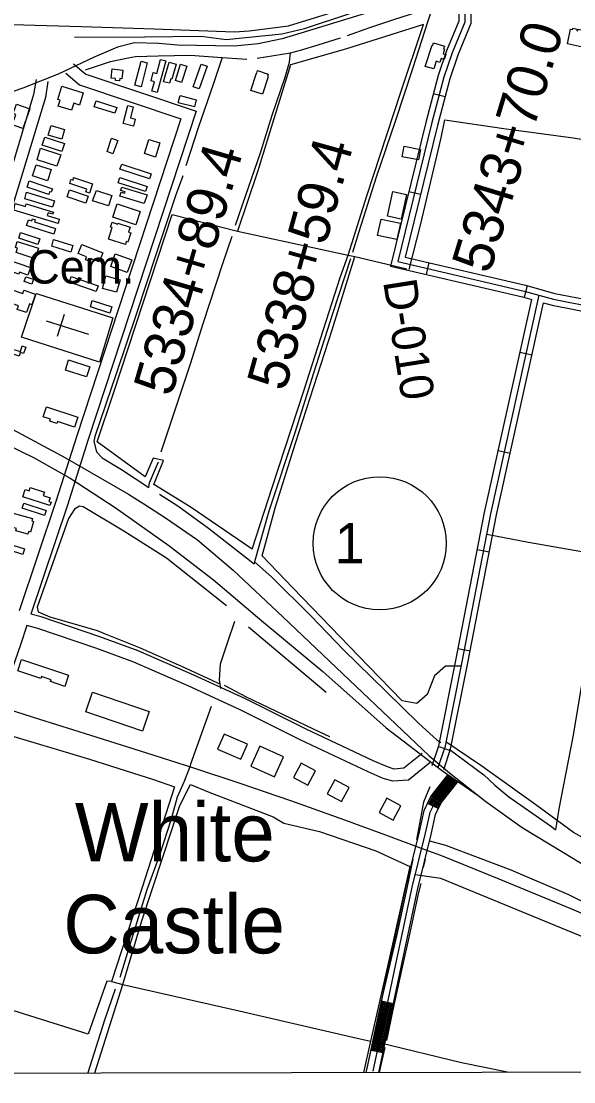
# Model space of a CAD drawing. Extents: x 3324125 to 3362000, y 600753 to 626151.
# Drawn here: x 3340770 to 3342140, y 606134 to 608764 of the extents above; entities that cross this region are included whole.
import ezdxf

# ---------------------------------------------------------------- set-up
doc = ezdxf.new("R2010")
doc.units = 0
for name, color, linetype in [('V-BLDG-OTLN', 7, 'Continuous'), ('V-DTCH-CNTR', 7, 'Continuous'), ('V-GRID-FRAM', 7, 'Continuous'), ('V-LEVE-TOET', 7, 'Continuous'), ('V-RAIL-TRAK', 7, 'Continuous'), ('V-RIVR-RANG-IDEN', 7, 'Continuous'), ('V-ROAD-CNTR', 7, 'Continuous'), ('V-ROAD-IDEN', 7, 'Continuous'), ('V-SITE-OTLN', 7, 'Continuous'), ('V-SITE-OTLN-IDEN', 7, 'Continuous'), ('V-SURV-IDEN', 7, 'Continuous'), ('V-TOPO-GNAM-IDEN', 7, 'Continuous'), ('V-TOPO-SHOR', 7, 'Continuous')]:
    doc.layers.add(name, color=color, linetype=linetype)

msp = doc.modelspace()

# ---------------------------------------------------------------- linework, layer by layer
at = {"layer": 'V-BLDG-OTLN'}
for points in [[(3342124.1, 608707.7), (3342131.5, 608744.4), (3342136.6, 608743.3), (3342137.4, 608746.9), (3342148.2, 608744.5), (3342147.4, 608740.8), (3342149.2, 608740.4), (3342150.1, 608744.6), (3342168.6, 608740.6), (3342163.5, 608717.5), (3342172.5, 608715.6), (3342168.6, 608697.9)], [(3341771.6, 608652.1), (3341788.3, 608705), (3341790.3, 608704.3), (3341792.2, 608710.4), (3341819.1, 608701.8), (3341817, 608695.2), (3341819.5, 608694.4), (3341816, 608683.4), (3341822.3, 608681.4), (3341818.5, 608669.5), (3341810.8, 608672), (3341807.6, 608661.7), (3341798.5, 608664.6), (3341792.7, 608645.6)], [(3341052.2, 608605.6), (3341067.4, 608664.7), (3341082.6, 608660.8), (3341067.4, 608601.5)], [(3341107.5, 608587.1), (3341094.3, 608590.7), (3341100.5, 608614.1), (3341091.9, 608616.3), (3341097.3, 608636.7), (3341106.3, 608634.3), (3341115.6, 608669.5), (3341128.3, 608666.1)], [(3340992.9, 608622.7), (3340995.6, 608645.9), (3341022.2, 608642.8), (3341019.7, 608621.2), (3341014.6, 608621.8), (3341013.9, 608615.9), (3341003.8, 608617.1), (3341004.3, 608621.7)], [(3341122.5, 608613.5), (3341137.1, 608662.5), (3341154.5, 608657.3), (3341143.6, 608620.7), (3341141.2, 608621.4), (3341137.9, 608610.3)], [(3341152.2, 608617.2), (3341165, 608657.2), (3341180.5, 608652.2), (3341167.7, 608612.3)], [(3341231.4, 608652.2), (3341211.3, 608596.3), (3341196.2, 608601.7), (3341216.4, 608657.6)], [(3341338.9, 608592.6), (3341353, 608635.6), (3341354.1, 608635.2), (3341356.1, 608641.5), (3341382.5, 608632.9), (3341380.4, 608626.6), (3341382.3, 608626), (3341368.3, 608583)], [(3340870.9, 608603), (3340923.8, 608586.8), (3340914.4, 608556.2), (3340900.4, 608560.5), (3340895.2, 608543.7), (3340862.1, 608553.8), (3340866.6, 608568.6), (3340860.9, 608570.3)], [(3340743.5, 608508.8), (3340747, 608522.4), (3340752.8, 608520.4), (3340757.1, 608532.8), (3340750.2, 608535.2), (3340758.4, 608558.6), (3340791.3, 608547.1), (3340774.1, 608498.1)], [(3340951.3, 608552.1), (3340955.6, 608566.5), (3341006.9, 608550.3), (3341002.4, 608536)], [(3341159.2, 608561.6), (3341164.3, 608580.2), (3341204.2, 608569.3), (3341199.8, 608551.5)], [(3341022.9, 608510.5), (3341034.3, 608554.8), (3341047.7, 608551.6), (3341041, 608524.1), (3341052.6, 608521.3), (3341048.4, 608504.2)], [(3340837.1, 608481.6), (3340844.2, 608505.7), (3340877.7, 608495.7), (3340870.5, 608471.6)], [(3340828.7, 608476.3), (3340877.4, 608460.8), (3340871.3, 608441.4), (3340822.1, 608457.1)], [(3340994.3, 608474.3), (3341009.9, 608468.4), (3340997.6, 608435.5), (3340983.5, 608440.8)], [(3341114, 608462.3), (3341102.8, 608427.3), (3341075.7, 608436), (3341086.9, 608471)], [(3341714.1, 608428.2), (3341719.2, 608454.2), (3341759.8, 608446.2), (3341754.7, 608420.2)], [(3340818.3, 608449.2), (3340868.1, 608433), (3340858.8, 608404.5), (3340809.4, 608420.6)], [(3340807.3, 608408.1), (3340844.2, 608396.4), (3340835.4, 608368.7), (3340798.6, 608380.4)], [(3341019.8, 608409.6), (3341092.2, 608385.4), (3341088.1, 608373.1), (3341015, 608397.5)], [(3340900.2, 608376.7), (3340946.9, 608360.8), (3340939.1, 608337.9), (3340930.1, 608341), (3340932.5, 608347.8), (3340890.8, 608361.8), (3340893.6, 608371.4), (3340898.8, 608369.9)], [(3341010.3, 608363.6), (3341014.6, 608376.6), (3341082.7, 608354.5), (3341078.5, 608341.5)], [(3340790, 608368.1), (3340847.4, 608348.4), (3340844.5, 608339.8), (3340840.6, 608341.1), (3340838.4, 608334.7), (3340785.1, 608353)], [(3341014.8, 608330.3), (3341017.7, 608340.3), (3341026.9, 608337.5), (3341027.9, 608340.7), (3341016.6, 608344.2), (3341019.3, 608353), (3341082.1, 608333.6), (3341075.3, 608311.7)], [(3340779.3, 608323.9), (3340783.2, 608340.5), (3340852.9, 608319.1), (3340847.9, 608302.8)], [(3340890.2, 608345.7), (3340936.2, 608330.2), (3340930.3, 608312.9), (3340884, 608328.5)], [(3340956.7, 608344.5), (3340994.9, 608332), (3340986.6, 608306.2), (3340947.2, 608319)], [(3341712, 608273.3), (3341677.7, 608280.8), (3341691.1, 608341.8), (3341725.4, 608334.3)], [(3340751.6, 608295.3), (3340755.6, 608312.5), (3340780.9, 608305), (3340782.8, 608311.1), (3340850.4, 608290.9), (3340848.7, 608285.4), (3340836.8, 608288.9), (3340834.8, 608282.2), (3340864.7, 608273.3), (3340861.5, 608262.5)], [(3341008.2, 608311.2), (3341065.3, 608292.2), (3341054.2, 608258.9), (3340996.9, 608278)], [(3340783.6, 608257.5), (3340788, 608271.7), (3340796.5, 608269), (3340798.2, 608274.3), (3340804.7, 608272.2), (3340803, 608266.9), (3340855.4, 608249.9), (3340850.8, 608235.7)], [(3341653.6, 608232.9), (3341662.5, 608273.5), (3341709.9, 608263), (3341701, 608222.5)], [(3340986.5, 608223.8), (3340995.3, 608252.7), (3340991.6, 608253.8), (3340995.4, 608265.5), (3341008.8, 608261.2), (3341009.4, 608263.1), (3341040.4, 608253.1), (3341036.5, 608241.2), (3341041.9, 608239.5), (3341034.5, 608216.3), (3341030.6, 608217.6), (3341028.3, 608210.4)], [(3340760.4, 608218.1), (3340813.3, 608201.2), (3340805, 608175.1), (3340757.5, 608190.3), (3340761.1, 608201.7), (3340756, 608203.4)], [(3340768.7, 608240.4), (3340816.1, 608224.5), (3340811.4, 608210.5), (3340764.4, 608226.3)], [(3340850.5, 608223.2), (3340898.5, 608208), (3340893.2, 608191.2), (3340846.1, 608206.1)], [(3340920.1, 608210.5), (3340972.7, 608189.7), (3340963.8, 608167.2), (3340943.8, 608175.1), (3340941.1, 608168.2), (3340929.5, 608172.8), (3340932.1, 608179.6), (3340911.2, 608187.8)], [(3340733.1, 608174.2), (3340793.3, 608153.5), (3340786.7, 608134.3), (3340765.6, 608141.5), (3340764, 608136.9), (3340721.7, 608151.4), (3340722.3, 608153.1), (3340719.6, 608154.1), (3340723.5, 608165.4), (3340729.2, 608163.5)], [(3341003.3, 608187), (3341044, 608172.8), (3341033, 608141.4), (3340992, 608155.6)], [(3340781.8, 608130.5), (3340800.6, 608124.7), (3340796.8, 608112.5), (3340777.5, 608118.6)], [(3340889.7, 608116.9), (3340894.1, 608130.9), (3340961, 608108), (3340956.2, 608094.1)], [(3340971.5, 608101.7), (3340980.1, 608132.7), (3341015.3, 608122.9), (3341006.7, 608092.2)], [(3340713, 608109.9), (3340773.9, 608089.1), (3340776.7, 608097.2), (3340805.3, 608087.5), (3340796.4, 608061.2), (3340790.4, 608063.3), (3340783.1, 608041.7), (3340760.2, 608049.5), (3340763.2, 608058.4), (3340701.3, 608079.5)], [(3340946.1, 608071.8), (3340995.2, 608055.5), (3340990, 608039.9), (3340942, 608055.8)], [(3340746.4, 607926.5), (3340719.7, 607932.8), (3340723.1, 607947.1), (3340747.9, 607940), (3340750.9, 607950.3), (3340768.1, 607944.9), (3340772.6, 607959.1), (3340781.5, 607956.3), (3340776.3, 607939.9), (3340767.9, 607942.6), (3340765.1, 607933.7), (3340750.1, 607938.4)], [(3340887.7, 607924.2), (3340939.9, 607906.9), (3340931.7, 607882.1), (3340880, 607899.2)], [(3340833, 607807.9), (3340910.3, 607782), (3340902.2, 607757.8), (3340860.4, 607771.8), (3340858.7, 607766.7), (3340841.4, 607772.5), (3340843, 607777.2), (3340824.9, 607783.3)], [(3340841.2, 607563.5), (3340774.2, 607585.2), (3340779.9, 607602.7), (3340789.8, 607599.5), (3340792.5, 607607.9), (3340827.6, 607596.5), (3340824.8, 607587.8), (3340841.6, 607582.3), (3340838.8, 607573.4), (3340844.3, 607571.7)], [(3340772.8, 607556.7), (3340776.4, 607569.1), (3340832.2, 607550.9), (3340828.2, 607538.7)], [(3340689.9, 607520.5), (3340697.1, 607546.4), (3340716.5, 607541), (3340719.8, 607552.6), (3340798, 607530.7), (3340796.4, 607525.1), (3340801, 607523.8), (3340793.6, 607497.4), (3340788.5, 607498.8), (3340786.7, 607492.4), (3340757.2, 607500.7), (3340758.7, 607506.2), (3340729.8, 607514.3), (3340728.5, 607509.7)], [(3340709.6, 607462.3), (3340714.1, 607475.9), (3340778.4, 607455.7), (3340774.1, 607442)], [(3340887.3, 607142.3), (3340878.3, 607114.6), (3340842.5, 607126.6), (3340844.2, 607131.5), (3340820.8, 607139.3), (3340819.1, 607134.3), (3340761.9, 607153.4), (3340771.2, 607181.1)], [(3340930.2, 607051.6), (3340946.6, 607100.4), (3341087.6, 607052.9), (3341071.1, 607004.1)], [(3341256.8, 606959.4), (3341314.5, 606934), (3341330.9, 606971.4), (3341273.2, 606996.7)], [(3341339.4, 606917), (3341398.1, 606891), (3341419.9, 606940.5), (3341361.2, 606966.4)], [(3341499.4, 606905.1), (3341464.1, 606924.1), (3341445.2, 606888.8), (3341480.4, 606869.9)], [(3341582.7, 606864.4), (3341547.5, 606883.3), (3341528.6, 606848.1), (3341563.8, 606829.1)], [(3341711.3, 606818.4), (3341676.1, 606837.3), (3341657.1, 606802.1), (3341692.3, 606783.1)]]:
    msp.add_lwpolyline(points, close=True, dxfattribs=at)
at = {"layer": 'V-DTCH-CNTR'}
for points in [[(3341580.8, 608184.3), (3341626.7, 608330.9), (3341710.1, 608585.6), (3341767.2, 608756.2), (3341573.6, 608695), (3341437.5, 608656.1), (3341355.8, 608390.3), (3341306.3, 608243.3)], [(3341731.7, 608148.7), (3341759.7, 608258.4), (3341810.6, 608474.5), (3341820, 608519.9), (3341966.5, 608498), (3342138, 608475.2), (3342300.8, 608448.1), (3342387.4, 608434.6)], [(3341342.3, 607454.7), (3341188.7, 607559.8), (3341098.6, 607615.3), (3341122.5, 607675.3), (3341097.6, 607680.4), (3341077.1, 607634.1), (3340958.7, 607721.2), (3340998.7, 607842.1), (3341144.2, 608284.6), (3341306.3, 608243.3), (3341580.8, 608184.3), (3341596.7, 608180.8)], [(3341342.3, 607454.7), (3341392.5, 607608.2), (3341471.7, 607850.1), (3341561, 608128.7), (3341580.8, 608184.3)], [(3341859.5, 607165.1), (3341821.8, 607165.1), (3341794.4, 607141), (3341776.5, 607094.7), (3341750.8, 607072.4), (3341714, 607079.1), (3341630.7, 607164.6), (3341443.4, 607359.6), (3341367, 607438.3), (3341400.1, 607560), (3341450.4, 607717.8), (3341540.6, 607999.1), (3341596.7, 608180.8), (3341725.8, 608149.8)], [(3342220.7, 607437.4), (3342027.8, 607471.3), (3341923.9, 607491.7)], [(3342220.7, 607437.4), (3342204.6, 607323.4), (3342315.2, 607298.8), (3342369.3, 607281.8), (3342340.5, 607099.2), (3342287.3, 606782.1), (3342270.3, 606679.2), (3342139.1, 606752.6), (3342045.5, 606820.9), (3341909.1, 606918.3), (3341822.3, 606977.7)], [(3340719.1, 607000.2), (3340939.5, 606934.7), (3341098.1, 606883.6), (3341150.4, 606865.7), (3341069.6, 606616.2), (3340993.8, 606383), (3340982.7, 606383.8), (3340935.9, 606252.6), (3340733.5, 606316.4), (3340517.4, 606386.2), (3340575.3, 606562), (3340655.3, 606803)], [(3340993.8, 606383), (3341022.1, 606376.1), (3341068, 606531.3), (3341120.8, 606691.7), (3341163.3, 606819.4), (3341189.8, 606871.8), (3341233.5, 606853), (3341394.7, 606791.7), (3341421.3, 606775.4), (3341509.7, 606755.1), (3341649.4, 606707.4), (3341733.5, 606668.2), (3341678.3, 606420.4), (3341635.6, 606234.9), (3341618.5, 606157.9)], [(3342331.2, 606159.1), (3342335.2, 606194.3), (3342356.1, 606410.3), (3342239.5, 606461.4), (3342025.1, 606550.1), (3341809.8, 606638.7), (3341746.2, 606648)], [(3340952.7, 606156.7), (3341022.1, 606376.1), (3341310.1, 606310.8), (3341592.2, 606245.4), (3341635.6, 606234.9)], [(3341657, 606231.6), (3341861.1, 606182.4), (3341979.4, 606158.5)]]:
    msp.add_lwpolyline(points, dxfattribs=at)
at = {"layer": 'V-GRID-FRAM'}
msp.add_lwpolyline([(3328210, 624318.2), (3328233.8, 606134.5), (3359834, 606189.7), (3359794.3, 624373.3), (3328210, 624318.2)], dxfattribs=at)
at = {"layer": 'V-LEVE-TOET'}
msp.add_lwpolyline([(3340396.7, 608772.9), (3340517.9, 608769.3), (3340748.2, 608755.5), (3340919.7, 608750.7), (3341099.8, 608745), (3341298.5, 608738.1), (3341335.3, 608740.4), (3341432.7, 608752.3), (3341564.2, 608792.8), (3341762.3, 608863.8), (3341963.8, 608949.1), (3342106.6, 609009.6), (3342255.4, 609075.3), (3342427, 609152.3), (3342591.8, 609224.6), (3342754, 609299.4), (3342881.1, 609361.6)], dxfattribs=at)
at = {"layer": 'V-RAIL-TRAK'}
msp.add_lwpolyline([(3342282.9, 606498.6), (3342135.1, 606562.9), (3341955, 606637.2), (3341809.8, 606695.2), (3341762.1, 606713.3), (3341673.7, 606745.6), (3341563, 606786.8), (3341438.5, 606831), (3341313.2, 606873.7), (3341195.2, 606912.8), (3341081.3, 606949.3), (3340942.5, 606993.3), (3340816.5, 607032.9), (3340699, 607069.6)], dxfattribs=at)
at = {"layer": 'V-ROAD-CNTR'}
for p, q in [((3341820.5, 608576.3), (3341791.4, 608583.8)), ((3341759.7, 608334), (3341730.6, 608341.1)), ((3341780.4, 608165.6), (3341773.6, 608136.4)), ((3342024.4, 608108.4), (3342016.4, 608079.5)), ((3342006.6, 607943.4), (3342035.9, 607936.9)), ((3341952.6, 607699.4), (3341981.8, 607692.9)), ((3341900.9, 607454.4), (3341930.3, 607448.7)), ((3341853.5, 607208.9), (3341882.9, 607203.2)), ((3341804.9, 606965.8), (3341833.3, 606956.1)), ((3341777.4, 606825.4), (3341804.2, 606811.9)), ((3341663.3, 606335.3), (3341692.6, 606329)), ((3341637.2, 606213), (3341666.5, 606206.8))]:
    msp.add_line(p, q, dxfattribs=at)
for points in [[(3341842.2, 608862.8), (3341855.4, 608817.4), (3341854.4, 608764.5), (3341824, 608690.5), (3341803.4, 608629.4), (3341772.9, 608513), (3341685.2, 608157), (3342012.7, 608080.5), (3342035.6, 608074.1)], [(3341856.6, 608867), (3341870.4, 608819.4), (3341869.3, 608761.4), (3341838.1, 608685.3), (3341817.7, 608625.1), (3341787.4, 608509.3), (3341703.4, 608168.2), (3342016.4, 608095), (3342089.5, 608074.7), (3342193.8, 608054.2), (3342282.1, 608035.2), (3342338.2, 608015.5), (3342391.3, 607995.9), (3342512.8, 607973.7), (3342573.7, 607967.2)], [(3341871, 608871.2), (3341885.5, 608821.4), (3341884.3, 608758.3), (3341852.1, 608680), (3341832.1, 608620.8), (3341802, 608505.7), (3341721.6, 608179.3), (3342020.1, 608109.6), (3342093, 608089.3), (3342196.8, 608068.9), (3342286.2, 608049.7), (3342343.3, 608029.6), (3342395.2, 608010.4), (3342514.9, 607988.6), (3342560.7, 607983.7)], [(3341671, 608798), (3341463.6, 608734.1), (3341416.7, 608720), (3341357.2, 608708.3), (3341298.6, 608702), (3341157.7, 608704.8), (3341111.7, 608708.4), (3341051.4, 608710.4), (3341009.1, 608699.7), (3340951.4, 608675.3), (3340861.5, 608633.1), (3340774.6, 608597.8), (3340730.9, 608583.3), (3340683.4, 608579.7), (3340637.3, 608577.7), (3340569.4, 608597.3), (3340273.9, 608693.1), (3340246.8, 608693.1), (3340227.9, 608682.5), (3340217.8, 608669.7), (3340203.5, 608644.2), (3340151.5, 608473.1)], [(3340899.8, 608658.1), (3340930, 608632.9), (3341203.9, 608540.9), (3340936.5, 607726.8), (3340884.9, 607564), (3340794.1, 607294.2)], [(3340836.6, 608614.5), (3340830.2, 608575.2), (3340725.1, 608227), (3340612.2, 607864.2), (3340584.7, 607755.8), (3340548.5, 607697.8), (3340461.7, 607414.7), (3340457.9, 607402)], [(3340807, 608619.3), (3340800.9, 608582), (3340696.5, 608235.8), (3340691.7, 608220.5)], [(3340880.6, 608635), (3340915.1, 608606.2), (3341166.1, 608521.9), (3340907.9, 607736), (3340856.4, 607573.3), (3340765.1, 607302.1)], [(3342053.3, 608084.8), (3341933.2, 607542.9), (3341862.4, 607175.8), (3341819.9, 606963.2), (3341803, 606913.6)], [(3341788.8, 606918.4), (3341805.3, 606967.1), (3341847.6, 607178.7), (3341918.6, 607545.9), (3342035.6, 608074.1)], [(3341817.2, 606908.8), (3341834.4, 606959.3), (3341877.1, 607172.9), (3341947.9, 607539.8), (3342064.6, 608066.1)], [(3342064.6, 608066.1), (3342086.1, 608060.1), (3342190.7, 608039.5), (3342278.1, 608020.8), (3342333.1, 608001.4), (3342387.3, 607981.3), (3342510.6, 607958.9), (3342556.9, 607953.9)], [(3340714.9, 607769.9), (3340880.1, 607681.8), (3341036.4, 607591.8), (3341074.3, 607567.1), (3341127.7, 607532.4), (3341207.4, 607477.8), (3341295.5, 607403), (3341418.8, 607287.4), (3341781.2, 606942.4), (3341831.7, 606900.8), (3341921.7, 606829.5), (3342012, 606765.2), (3342114.3, 606702.9), (3342228.3, 606633.2)], [(3340664.6, 607748.6), (3340802.7, 607681.7), (3340891.7, 607630.7), (3341002.8, 607558.3), (3341136, 607464.3), (3341246.6, 607379.3), (3341366.9, 607277.5), (3341517.7, 607151.7), (3341674.6, 607012.2), (3341811.8, 606906.8), (3341903, 606844.3)], [(3341763.6, 606948.3), (3341718.3, 606911.7), (3341694.6, 606909.9), (3341677.8, 606915), (3341642.3, 606930), (3341474.8, 607009.2), (3341325.7, 607084), (3341198.2, 607142.5), (3341060.4, 607203.1), (3340965, 607237.9), (3340819.9, 607287.2), (3340794.1, 607294.2)], [(3340784.5, 607265.8), (3340768.3, 607217.6), (3340683.2, 606974.6), (3340572.3, 606625.3), (3340477.1, 606345), (3340245.4, 606418.3), (3340202.5, 606434.2)], [(3341782.5, 606924.9), (3341729.8, 606882.4), (3341691.3, 606879.6), (3341667.6, 606886.8), (3341630.1, 606902.6), (3341461.6, 606982.2), (3341312.8, 607057), (3341185.9, 607115.2), (3341049.3, 607175.3), (3340955.1, 607209.6), (3340811.1, 607258.5), (3340784.5, 607265.8)], [(3341626.8, 606164.1), (3341724.1, 606620.3), (3341756.9, 606754.4), (3341768.5, 606807.5), (3341785.7, 606842), (3341828.6, 606896.5)], [(3341840.4, 606887.3), (3341798.5, 606833.9), (3341782.7, 606802.5), (3341771.5, 606751), (3341738.7, 606617), (3341641.4, 606161)], [(3341656.1, 606157.9), (3341753.4, 606613.6), (3341786.2, 606747.6), (3341797, 606797.5), (3341811.2, 606825.9), (3341852.1, 606878)], [(3341780.1, 606824), (3341788.3, 606840.4), (3341830.9, 606894.7)], [(3341782.8, 606822.7), (3341790.8, 606838.8), (3341833.3, 606892.8)], [(3341785.5, 606821.3), (3341793.4, 606837.2), (3341835.6, 606891)], [(3341788.1, 606820), (3341795.9, 606835.5), (3341838, 606889.1)], [(3341790.8, 606818.6), (3341798.5, 606833.9), (3341840.4, 606887.3)], [(3341793.5, 606817.3), (3341801, 606832.3), (3341842.7, 606885.4)], [(3341796.2, 606816), (3341803.6, 606830.7), (3341845.1, 606883.6)], [(3341798.9, 606814.6), (3341806.1, 606829.1), (3341847.4, 606881.7)], [(3341801.5, 606813.3), (3341808.7, 606827.5), (3341849.8, 606879.8)], [(3341640.1, 606212.4), (3341666.2, 606334.6)], [(3341643.1, 606211.8), (3341669.2, 606334)], [(3341646, 606211.1), (3341672.1, 606333.4)], [(3341648.9, 606210.5), (3341675, 606332.8)], [(3341651.9, 606209.9), (3341678, 606332.1)], [(3341654.8, 606209.3), (3341680.9, 606331.5)], [(3341657.7, 606208.6), (3341683.8, 606330.9)], [(3341660.7, 606208), (3341686.8, 606330.3)], [(3341663.6, 606207.4), (3341689.7, 606329.6)]]:
    msp.add_lwpolyline(points, dxfattribs=at)
at = {"layer": 'V-ROAD-IDEN'}
msp.add_circle((3341658.7, 607469.6), 165, dxfattribs=at)
at = {"layer": 'V-SITE-OTLN'}
for p, q in [((3340876.4, 608036.8), (3340859.4, 607982.5)), ((3340938, 607987.7), (3340832.8, 608020.6))]:
    msp.add_line(p, q, dxfattribs=at)
msp.add_lwpolyline([(3340810.3, 608087.9), (3340997.6, 608028.9), (3340964.5, 607919), (3340771.1, 607980.5), (3340807.2, 608088.8)], close=True, dxfattribs=at)
at = {"layer": 'V-TOPO-SHOR'}
for p, q in [((3341333.3, 607262.6), (3341526.4, 607100.4)), ((3341241.1, 607064.8), (3341190, 606921.6)), ((3341767.2, 606665.6), (3341772.3, 606686.8))]:
    msp.add_line(p, q, dxfattribs=at)
for points in [[(3340902.7, 608724.9), (3341076.6, 608725.1), (3341216.6, 608726.8), (3341278.5, 608718.5), (3341416, 608732.5), (3341472.5, 608746.1), (3341584.4, 608783.4), (3341727.4, 608830.4), (3341822.7, 608866.9), (3341919.6, 608906.4), (3342028.1, 608954.3), (3342153.1, 609012.2), (3342216, 609038.9), (3342285.9, 609072.6), (3342358.4, 609103.8), (3342418.6, 609131.9), (3342526.2, 609178.2), (3342656.4, 609238.6), (3342777.1, 609291.8), (3342859, 609330.6), (3342962.7, 609376.3), (3343022.3, 609405.6), (3343100.7, 609441.6), (3343235.8, 609496.9)], [(3341578.9, 608728.3), (3341634.6, 608748.1), (3341693.3, 608768), (3341789.1, 608798.8), (3341777.6, 608764.2), (3341739.7, 608645.7), (3341697.3, 608515.4), (3341650.3, 608377.7), (3341607.3, 608241.7), (3341591.2, 608190.7)], [(3341354.6, 608672.4), (3341437.4, 608686), (3341462.3, 608692.6), (3341506.2, 608705.3), (3341561.6, 608722.5)], [(3340929.5, 608643.6), (3340991.5, 608664.1), (3341035.6, 608673.5), (3341053.1, 608676.8), (3341109.9, 608678.4), (3341188.7, 608680.2), (3341268.1, 608674.3), (3341329, 608669.8)], [(3341268.1, 608674.3), (3341245.8, 608607.3), (3341209.3, 608502.4), (3341178.4, 608405.3)], [(3341301.6, 608258.2), (3341327.1, 608332.9), (3341363.4, 608437.7), (3341392.1, 608531.2), (3341424.1, 608625.7), (3341435.5, 608662.7), (3341437.4, 608686)], [(3341170.4, 608380.8), (3341152.3, 608331.2), (3341104.3, 608187.7), (3341054.8, 608036.5), (3341006.1, 607892.6), (3340952.6, 607734.8), (3340949.9, 607721.6), (3340956.9, 607696.6), (3340970.7, 607681.6), (3341018.6, 607652.9), (3341086.7, 607608)], [(3341117.3, 607696.2), (3341154.2, 607807.6), (3341189.5, 607914.3), (3341221.5, 608014.3), (3341270.1, 608163.6), (3341293, 608231.2)], [(3341585.9, 608174.5), (3341541.8, 608038.9), (3341494.3, 607891.7), (3341448.4, 607743.6), (3341384.1, 607549.2), (3341348.7, 607423.8), (3341347.4, 607419)], [(3341086.7, 607608), (3341087.8, 607619.6), (3341110.1, 607671.5)], [(3341113.1, 607591.8), (3341158.5, 607562.3), (3341234.1, 607507.1), (3341347.4, 607419)], [(3341279.2, 607314.8), (3341130.6, 607432.6), (3341024.4, 607500.1), (3340923.9, 607560), (3340914.3, 607561.9), (3340902.7, 607554.2), (3340887.3, 607531), (3340810, 607310.9), (3340812, 607299.3), (3340840.9, 607287.7), (3340958.7, 607253), (3340978, 607245.3), (3341064.9, 607210.5), (3341169.2, 607164.2), (3341240.6, 607131.3), (3341259.9, 607121.7)], [(3341348.7, 607423.8), (3341390.4, 607386.1), (3341489.1, 607289.1), (3341568.8, 607205.6), (3341673.9, 607102.9), (3341755.4, 607022.5), (3341800.5, 606982.6), (3341809.9, 606976)], [(3342213.4, 607421.8), (3342192.3, 607304.9), (3342165, 607157.9), (3342137.5, 606989.4), (3342102.5, 606811.6), (3342094.3, 606759.2)], [(3341298.9, 607276.1), (3341281.3, 607224.8), (3341263.5, 607170.3), (3341260.6, 607131), (3341264.5, 607109.9)], [(3341273.5, 607117.8), (3341327.5, 607088.9), (3341493.6, 607009.7), (3341534.1, 606990.4)], [(3341830.5, 606959.3), (3341916.6, 606895.5), (3341943.9, 606869.8), (3341978.3, 606841.3), (3342084.5, 606767.5), (3342094.3, 606759.2)], [(3341190, 606921.6), (3341187.9, 606915.1), (3341173.5, 606877.3), (3341157, 606840.2), (3341141, 606783), (3341113.7, 606699.1), (3341081.4, 606610.2), (3341049.7, 606506), (3341014.3, 606393)], [(3341783.3, 606865.6), (3341767.3, 606828.1), (3341750, 606735.5)], [(3341782.3, 606731.8), (3341822, 606721.4), (3341983.7, 606659.9), (3342126.2, 606599), (3342250.6, 606538), (3342373.5, 606484)], [(3341741.1, 606686.7), (3341725.5, 606614.3), (3341701, 606499.9), (3341667.5, 606355.7), (3341645, 606253.1)], [(3341676.7, 606237.2), (3341692.4, 606313.2), (3341713.4, 606410.9), (3341734.5, 606503.9), (3341754.7, 606600.2), (3341761.2, 606626.2)], [(3341003, 606363.8), (3340976.8, 606286.9), (3340935.3, 606156.7)], [(3341639.2, 606224.8), (3341624.4, 606157.9)], [(3341658.5, 606157.9), (3341664.9, 606187.2), (3341672.6, 606219.5)]]:
    msp.add_lwpolyline(points, dxfattribs=at)

# ---------------------------------------------------------------- texts
at = {"layer": 'V-RIVR-RANG-IDEN'}
msp.add_text('D-010', height=83, rotation=278.9543, dxfattribs=at).set_placement((3341666.8, 608118.6))
at = {"layer": 'V-ROAD-IDEN'}
msp.add_text(' 1 ', height=100, rotation=359.9873, dxfattribs=at).set_placement((3341509.9, 607419.6))
at = {"layer": 'V-SITE-OTLN-IDEN'}
msp.add_text('Cem.', height=83, dxfattribs=at).set_placement((3340785.5, 608113.5))
at = {"layer": 'V-SURV-IDEN'}
for s, rotation, p in [('5343+70.0', 73.1277, (3341931, 608134.6)), ('5334+89.4', 73.7327, (3341142.6, 607830.4)), ('5338+59.4', 74.5304, (3341424.4, 607843.6))]:
    msp.add_text(s, height=100, rotation=rotation, dxfattribs=at).set_placement(p)
at = {"layer": 'V-TOPO-GNAM-IDEN'}
for s, p in [('White', (3340903.1, 606681)), (' Castle', (3340820.4, 606453))]:
    msp.add_text(s, height=145, rotation=359.9873, dxfattribs=at).set_placement(p)

doc.saveas('drawing.dxf')
